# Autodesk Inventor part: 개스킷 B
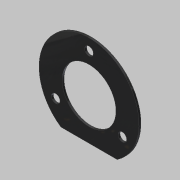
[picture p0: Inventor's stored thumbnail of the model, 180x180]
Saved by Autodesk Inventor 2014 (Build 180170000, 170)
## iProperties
Created: 2020-04
Part Number: 개스킷 B
Material: 고무
Document SubType Name: Modeling
Designer: mduedu
Density: 0.93 g/cm^3
Appearance: Rubber - Black - Version 1.1
Mass: 1.27493 g
Surface Area: 30.3371 cm^2
Volume: 1.37089 cm^3
Author: mduedu
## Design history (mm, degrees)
sketch "스케치1"
  geometry: C1 r 26 at (0, 0); 1 further point
  constraints: 1 centre point, 1 coincident
  dimensions: "d0" = 52 diameter of C1
extrude "돌출1" new body sketch "스케치1" distance "d1" = 1; taper "d2" = 0 deg
sketch "스케치2"
  geometry: L1 (-14.62, -21.5)-(14.62, -21.5); A1 r 26 centre (0, 0) between (-14.62, -21.5) and (14.62, -21.5) reference; 1 further point
  constraints: 2 end point, 2 point on circle, 1 horizontal
  dimensions: "d3" = 21.5 distance from line of L1 point (0, 0)
extrude "돌출2" cut sketch "스케치2" stored distance "d4" = 1; taper "d5" = 0 deg
sketch "스케치3" dims "d6" = 40
  geometry: 3 further points
  constraints: 2 vertical alignment, 1 coincident, 2 other
hole "구멍1" sketch "스케치3" at (0, 20) diameter "d7" = 4.5; stored, may be unused: countersink angle "d11" = 90 deg, drill point angle "d13" = 118 deg; dims "d8" = 6, "d9" = 4, "d10" = 2, "d12" = 8
sketch "스케치4"
  geometry: C1 r 14 at (0, 0); 1 further point
  constraints: 1 centre point, 1 coincident
  dimensions: "d17" = 28 diameter of C1
extrude "돌출3" cut sketch "스케치4" stored distance "d18" = 1; taper "d19" = 0 deg
node "솔리드1"
pattern_circular "원형 패턴1" dims angle "d15" = 360 deg
node "투영된 루프1"
